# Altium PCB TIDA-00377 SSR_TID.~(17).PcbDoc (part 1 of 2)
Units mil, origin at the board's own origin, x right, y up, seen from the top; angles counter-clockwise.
Board outline 4300 x 2000 mil, 2 copper layers (Layer 1 - Top Layer, Layer 2 - Bottom Layer), stack 62 mil thick; 114 components, 37 nets, 228 pads, 275 vias.
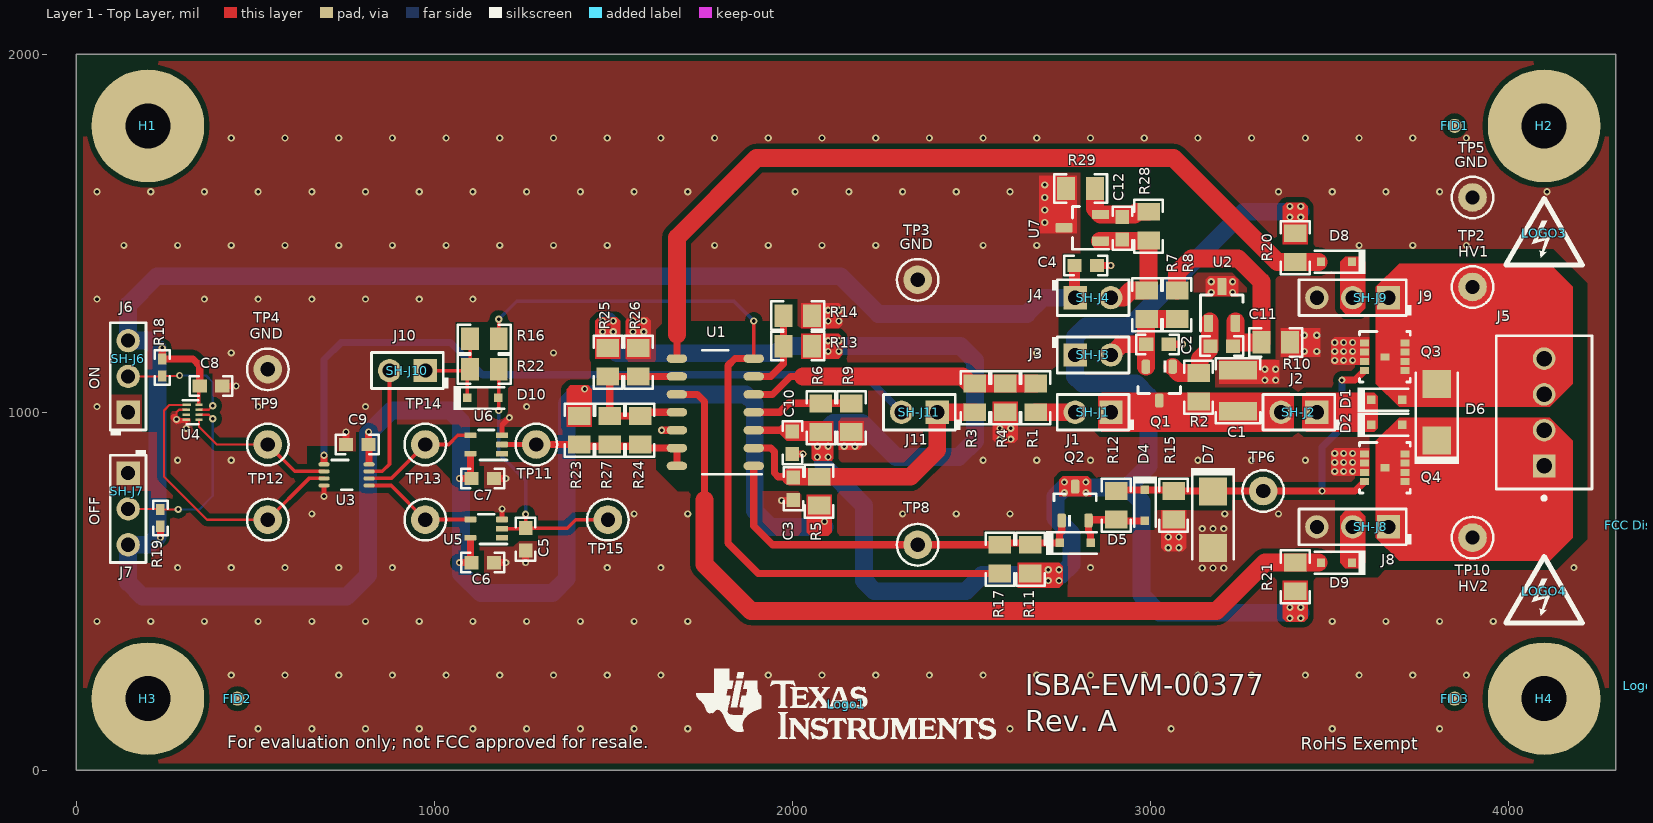
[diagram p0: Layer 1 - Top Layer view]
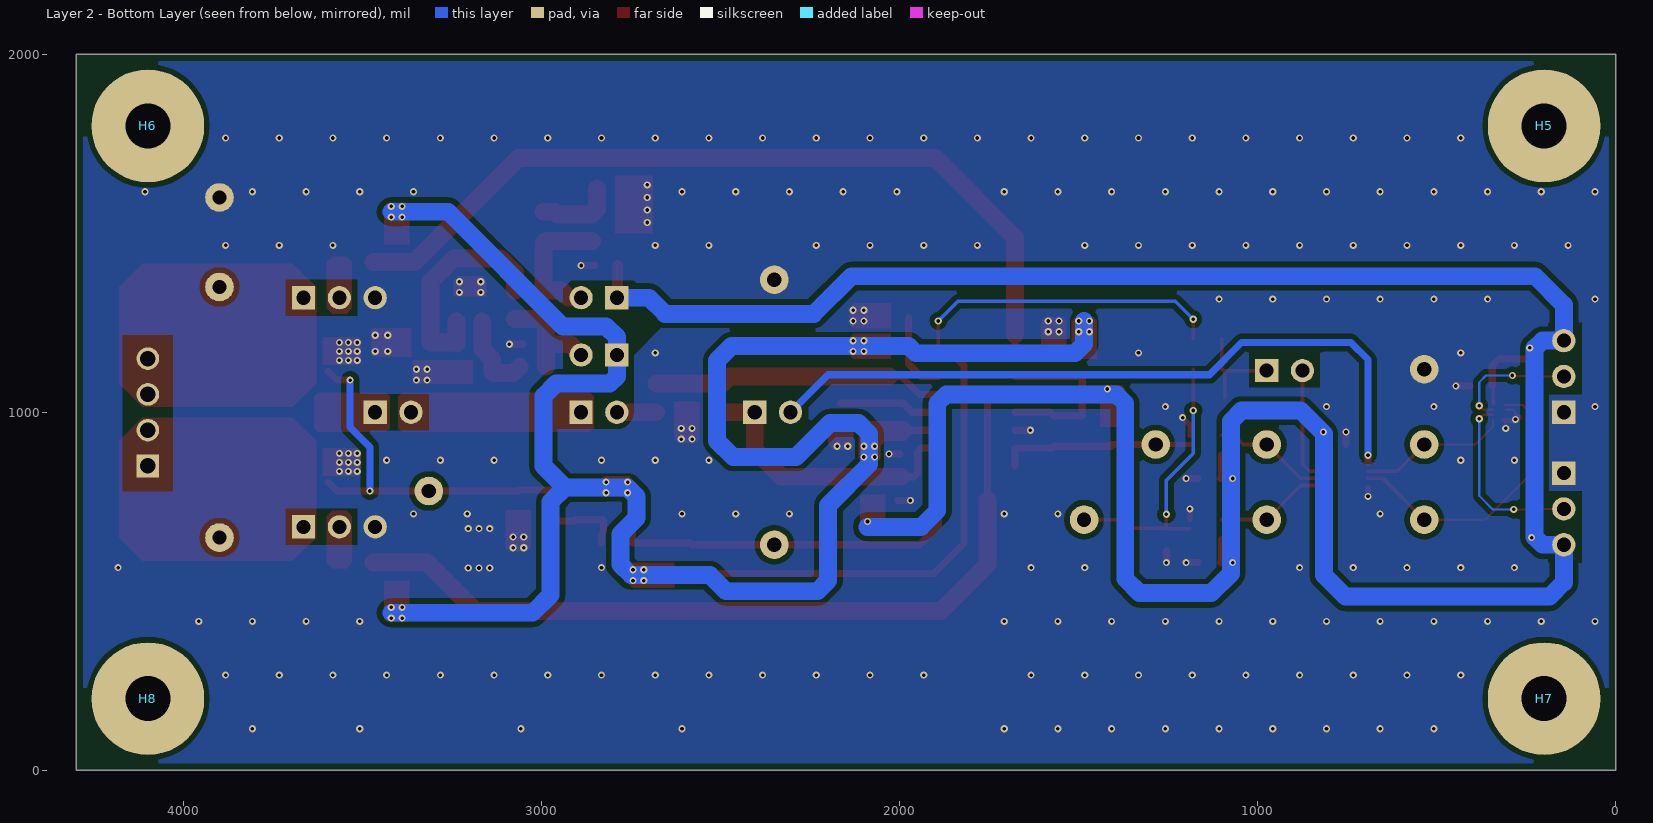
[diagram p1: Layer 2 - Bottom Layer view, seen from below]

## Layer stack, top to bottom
Top Solder: solder mask 0.4, Solder Resist, Dk 3.5
Layer 1 - Top Layer: signal copper 1.4
Dielectric1: core 59.2, 370HR, Dk 4.8
Layer 2 - Bottom Layer: signal copper 1.4
Bottom Solder: solder mask 0.4, Solder Resist, Dk 3.5

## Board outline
0,0 0,2000 4300,2000 4300,0

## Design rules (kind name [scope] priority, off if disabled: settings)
AcuteAngle [All] p1: minimum=4.50000000000000E+0001 checktracksonly=FALSE
AssemblyTestPointUsage [All] p1: valid=2
Clearance Clearance_Keepouts [((IsTrack Or IsArc) And Not InPoly) And IsFree and IsKeepOut vs ((IsTrack Or IsArc) And Not InPoly) And IsFree and IsKeepOut] p1: gap=0
Clearance Clearance_BoardEdge_MountingHoles [OnCopper and InComponentClass('Mounting Holes') vs IsKeepOut] p2: gap=40
Clearance Clearance_BoardEdge_Poly [OnCopper and InPoly vs IsKeepOut] p3: gap=20
Clearance Clearance_BoardEdge [OnCopper and Not InComponentClass('Logo') and not InComponentClass('FiducialMark') and not InRegion(1000,500,4000,800) and Not IsKeepout vs IsKeepOut] p4: gap=25
Clearance Clearance_Poly [InPolygon] p5: gap=15
Clearance [All] p6: gap=5.9
ComponentClearance ComponentClearance_MountingHoles_FiducialMarks [InComponentClass('Mounting Holes') vs InComponentClass('FiducialMark')] p1: gap=10 collisioncheckmode=3 verticalgap=10 showdistances=FALSE
ComponentClearance ComponentClearance_Shunt [InComponentClass('Header') vs InComponentClass('Shunt')] p2: gap=0 collisioncheckmode=3 verticalgap=0 showdistances=FALSE
ComponentClearance ComponentClearance_Logo [InComponentClass('Logo')] p3: gap=10 collisioncheckmode=3 verticalgap=10 showdistances=FALSE
ComponentClearance ComponentClearance_ScrewToNut [(HasFootprint('NY PMS 440 0025 PH')) vs (HasFootprint('Keystone_1902C'))] p4: gap=5 collisioncheckmode=3 verticalgap=10 showdistances=FALSE
ComponentClearance ComponentClearance_MountingHoles [InComponentClass('Mounting Holes')] p5: gap=10 collisioncheckmode=3 verticalgap=100000 showdistances=FALSE
ComponentClearance ComponentClearance_SmallPassives [HasFootprint('0201*') or HasFootprint('0402*') or HasFootprint('0508') or HasFootprint('0603*') or HasFootprint('0612') or HasFootprint('0805*') or HasFootprint('0815*') or HasFootprint('0830*') or HasFootprint('1206*') or HasFootprint('1210*') or HasFootprint('1808*') or HasFootprint('1812*') or HasFootprint('1825*') or HasFootprint('2010*') or HasFootprint('2220*') or HasFootprint('2225*') or HasFootprint('2512*') or HasFootprint('2728*') or HasFootprint('3518*') vs HasFootprint('0201*') or HasFootprint('0402*') or HasFootprint('0508') or HasFootprint('0603*') or HasFootprint('0612') or HasFootprint('0805*') or HasFootprint('0815*') or HasFootprint('0830*') or HasFootprint('1206*') or HasFootprint('1210*') or HasFootprint('1808*') or HasFootprint('1812*') or HasFootprint('1825*') or HasFootprint('2010*') or HasFootprint('2220*') or HasFootprint('2225*') or HasFootprint('2512*') or HasFootprint('2728*') or HasFootprint('3518*')] p6: gap=10 collisioncheckmode=3 verticalgap=10 showdistances=FALSE
ComponentClearance ComponentClearance_THtoSMT [IsThruComponent vs IsSMTComponent] p7: gap=10 collisioncheckmode=3 verticalgap=30 showdistances=FALSE
ComponentClearance ComponentClearance_THtoTH [IsThruComponent vs IsThruComponent] p8: gap=10 collisioncheckmode=3 verticalgap=30 showdistances=FALSE
ComponentClearance [All] p9: gap=10 collisioncheckmode=3 verticalgap=10 showdistances=FALSE
DiffPairsRouting [All] p1: maxlimit=100 minlimit=10 mostfreqgap=10 toplayer_minwidth=15 toplayer_maxwidth=15 toplayer_prefwidth=15 bottomlayer_minwidth=15 bottomlayer_maxwidth=15 bottomlayer_prefwidth=15 maxuncoupledlength=1000
FabricationTestPointUsage TestPointUsage [All] p1: valid=2 allowmultiple=FALSE
FabricationTestpoint Testpoint [All] p1: side=3 testpointundercomponent=TRUE minsize=40 maxsize=100 preferedsize=60 minholesize=0 maxholesize=40 preferedholesize=32 testpointgrid=1 allowsidetop=TRUE allowsidebottom=TRUE usegrid=TRUE gridtolerance=0.01
FanoutControl Fanout_LCC [IsLCC] p1: bgadir=Out bgaviamode=Centered fanoutstyle=Auto fanoutdirection=Alternating viagrid=1 // Fanout_LCC (Default Rule)
FanoutControl Fanout_BGA [IsBGA] p2: bgadir=Out bgaviamode=Centered fanoutstyle=Auto fanoutdirection=Alternating viagrid=1 // Fanout_BGA (Default Rule)
FanoutControl Fanout_Default [All] p4: bgadir=Out bgaviamode=Centered fanoutstyle=Auto fanoutdirection=Alternating viagrid=1 // Fanout_Default (Default Rule)
FanoutControl Fanout_Small [(CompPinCount < 5)] p5: bgadir=Out bgaviamode=Centered fanoutstyle=Auto fanoutdirection=OutThenIn viagrid=1 // Fanout_Small (Default Rule)
HoleSize [All] p1: absolutevalues=TRUE maxlimit=251 minlimit=8 maxpercent=80.000 minpercent=20.000
MinimumAnnularRing MinimumAnnularRing_ThermalPadVias [IsVia and InAnyComponent] p1: minimumring=5
MinimumAnnularRing [All] p2: minimumring=5
MinimumSolderMaskSliver MinimumSolderMaskSliver_Logo [InComponentClass('Logo') vs InComponentClass('Logo')] p1: minsoldermaskwidth=0.7
MinimumSolderMaskSliver [All] p2: minsoldermaskwidth=4
PlaneConnect [All] p1: planeconnectstyle=Relief reliefexpansion=10 reliefentries=4 reliefconductorwidth=10 reliefairgap=10
PolygonConnect [All] p1: connectstyle=Direct reliefconductorwidth=10 reliefentries=4 polygonreliefangle="90 Angle" airgapwidth=10
RoutingVias ThermalPadVias [IsVia and InAnyComponent] p1: holewidth=7.87 width=19.68 viastyle="Through Hole" minholewidth=7.87 minwidth=19.68 maxholewidth=12.99 maxwidth=23.62
RoutingVias [All] p2: holewidth=16 width=34 viastyle="Through Hole" minholewidth=7.87 minwidth=20 maxholewidth=40 maxwidth=65
SilkToBoardRegionClearance [Not ((IsComment or IsDesignator) And (Hide <> 'False')) and not InRegion(1000,500,4000,800)] p1:
SilkToSilkClearance SilkToSilkClearance_Pb-FreeLogo [(HasFootprint('Pb-Free_Overlay_Medium') OR HasFootprint('Pb-Free_Overlay_Small')) vs (HasFootprint('Pb-Free_Overlay_Medium') OR HasFootprint('Pb-Free_Overlay_Small'))] p1: silktosilkclearance=0
SilkToSilkClearance [All] p2: silktosilkclearance=4
SilkToSolderMaskClearance SilkToComonentPadClearance [IsPad and InAnycomponent] p1: minsilkscreentomaskgap=5 clearancetoexposedcopper=TRUE
SilkToSolderMaskClearance "Silk to Solder Mask Opening" [All] p2: minsilkscreentomaskgap=4 clearancetoexposedcopper=FALSE
SolderMaskExpansion [All] p1: expansion=1.97
Width [All] p1: maxlimit=100 minlimit=6 preferedwidth=10 checkconnectedcopper=TRUE
15 further rules are at their usual default settings.

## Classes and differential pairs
component class "TIDA-00377 SSR_Relay": C1 C2 C3 C4 C5 C6 C7 C8 C9 C10 C11 C12 D1 D2 D4 D5 D6 D7 D8 D9 D10 J1 J2 J3 J4 J5 J6 J7 J8 J9 J10 J11 Q1 Q2 Q3 Q4 R1 R2 R3 R4 R5 R6 R7 R8 R9 R10 R11 R12 R13 R14 R15 R16 R17 R18 R19 R20 R21 R22 R23 R24 R25 R26 R27 R28 R29 TP2 TP3 TP4 TP5 TP6 TP8 TP9 TP10 TP11 TP12 TP13 TP14 TP15 U1 U2 U3 U4 U5 U6 U7
component class Header: J1 J2 J3 J4 J6 J7 J8 J9 J10 J11
component class AssemblyNote: ZZ1 ZZ2 ZZ3
component class FiducialMark: FID1 FID2 FID3
component class "TIDA-00377 SSR_TID_Hardware": "FCC Disclaimer" FID1 FID2 FID3 H1 H2 H3 H4 H5 H6 H7 H8 Logo1 LOGO3 LOGO4 Logo? SH-J1 SH-J2 SH-J3 SH-J4 SH-J6 SH-J7 SH-J8 SH-J9 SH-J10 SH-J11 ZZ1 ZZ2 ZZ3
component class Logo: Logo1
component class "Mounting Holes": H1 H2 H3 H4
component class Shunt: SH-J1 SH-J2 SH-J3 SH-J4 SH-J6 SH-J7 SH-J8 SH-J9 SH-J10 SH-J11

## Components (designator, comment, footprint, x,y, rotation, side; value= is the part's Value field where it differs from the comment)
C1 "C3225X7S2A335M200AB" 1210 3245,1060 r270 top
C2 "GRM188R61E105KA12D" 0603 3020,1190 r180 top
C3 "GRM188R71E102KA01D" 0603 2003,786 r90 top
C4 "GRM188R61E105KA12D" 0603 2820,1410 r180 top
C5 "GRM188R71E102KA01D" 0603 1255,645 r90 top
C6 "GRM188R71C104KA01D" 0603 1135,580 r180 top
C7 "GRM188R71C104KA01D" 0603 1135,815 r180 top
C8 "GRM188R71C104KA01D" 0603 376.4,1073.3 r180 top
C9 "GRM188R71C104KA01D" 0603 785,910 r0 top
C10 "GRM188R71C104KA01D" 0603 2000,915 r90 top
C11 "GRM1885C1H201JA01D" 0603 3200,1184.68 r180 top
C12 "GRM1885C1H201JA01D" 0603 2922,1514.31 r270 top
D1 "1N4448WX-TP" sod-323 3660,1035 r0 top
D2 "1N4448WX-TP" sod-323 3660,965 r0 top
D4 "1N4448WX-TP" sod-323 2985,740 r270 top
D5 "1N4448WX-TP" sod-323 2790,635 r0 top
D6 "SMAJ78CA" SMA 3800,1000 r90 top
D7 "SMAZ18-13-F" SMA 3175,700 r270 top
D8 "1N4448WX-TP" sod-323 3520,1420 r180 top
D9 "1N4448WX-TP" sod-323 3520,580 r180 top
D10 "1N4448WX-TP" sod-323 1135,1040 r0 top
"FCC Disclaimer" "FCC disclaimer" FCC_disclaimer 4400,685 r90 top
FID1 "Fiducial" Fiducial10-20 3850,1800 r0 top
FID2 "Fiducial" Fiducial10-20 450,200 r0 top
FID3 "Fiducial" Fiducial10-20 3850,200 r0 top
H1 "NY PMS 440 0025 PH" "NY PMS 440 0025 PH" 200,1800 r0 top locked
H2 "NY PMS 440 0025 PH" "NY PMS 440 0025 PH" 4100,1800 r0 top locked
H3 "NY PMS 440 0025 PH" "NY PMS 440 0025 PH" 200,200 r0 top locked
H4 "NY PMS 440 0025 PH" "NY PMS 440 0025 PH" 4100,200 r0 top locked
H5 "1902C" Keystone_1902C 200,1800 r180 bottom locked
H6 "1902C" Keystone_1902C 4100,1800 r180 bottom locked
H7 "1902C" Keystone_1902C 200,200 r180 bottom locked
H8 "1902C" Keystone_1902C 4100,200 r180 bottom locked
J1 "5-146278-2" TE_5-146278-2 2840,1000 r180 top
J2 "5-146278-2" TE_5-146278-2 3415,1000 r180 top
J3 "5-146278-2" TE_5-146278-2 2840,1160 r0 top
J4 "5-146278-2" TE_5-146278-2 2840,1320 r0 top
J5 "282834-4" TEC_282834-4 4100,1000 r90 top
J6 "5-146278-3" TE_5-146278-3 145,1100 r90 top
J7 "5-146278-3" TE_5-146278-3 145,730 r270 top
J8 "5-146278-3" TE_5-146278-3 3565,680 r180 top
J9 "5-146278-3" TE_5-146278-3 3565,1320 r180 top
J10 "5-146278-2" TE_5-146278-2 925,1116.5 r180 top
J11 "5-146278-2" TE_5-146278-2 2355,1000 r180 top
Logo1 "Texas Instruments" TI_Stacked_Overlay_Small 2150,185 r0 top
LOGO3 "DANGER HIGH VOLTAGE" IEC_HighVoltage_Small 4100,1500 r0 top
LOGO4 "DANGER HIGH VOLTAGE" IEC_HighVoltage_Small 4100,500 r0 top
Logo? "EU RoHS Exempt Logo" EURoHS_Exempt_60mil 4373,236 r90 top
Q1 "DSC2C01R0L" SOT-23 3025,1080 r270 top
Q2 "MMBT3904LT1G" SOT-23 2790,745 r90 top
Q3 "CSD19537Q3" DQG0008A 3655,1155 r0 top
Q4 "CSD19537Q3" DQG0008A 3655,845 r0 top
R1 "CRCW080510M0FKEA" 0805_HV 2680,1040 r90 top
R2 "CRCW0805205KFKEA" 0805_HV 3135,1070 r90 top
R3 "CRCW08050000Z0EA" 0805_HV 2510,1040 r90 top
R4 "CRCW08051M43FKEA" 0805_HV 2595,1040 r270 top
R5 "CRCW0805100KFKEA" 0805_HV 2075,780 r90 top
R6 "CRCW080510M0FKEA" 0805_HV 2080,985 r90 top
R7 "CRCW0805100KFKEA" 0805_HV 2990,1300 r90 top
R8 "CRCW08053M74FKEA" 0805_HV 3075,1300 r90 top
R9 "CRCW08052M94FKEA" 0805_HV 2165,985 r270 top
R10 "CRCW08051M30FKEA" 0805_HV 3350,1195 r0 top
R11 "CRCW080593K1FKEA" 0805_HV 2665,590 r90 top
R12 "CRCW0805931RFKEA" 0805_HV 2905,740 r90 top
R13 "RC0805JR-0733ML" 0805_HV 2015,1185 r180 top
R14 "CRCW08056M49FKEA" 0805_HV 2015,1270 r0 top
R15 "CRCW0805422KFKEA" 0805_HV 3065,740 r90 top
R16 "CRCW08050000Z0EA" 0805_HV 1140,1205 r0 top
R17 "CRCW08050000Z0EA" 0805_HV 2580,590 r90 top
R18 "CRCW0402124KFKED" 0402 240,1125 r90 top
R19 "CRCW0402124KFKED" 0402 235,705 r270 top
R20 "RC0805JR-0733ML" 0805_HV 3405,1460 r270 top
R21 "RC0805JR-0733ML" 0805_HV 3405,540 r90 top
R22 "CRCW0805100KFKEA" 0805_HV 1140,1120 r0 top
R23 "CRCW0805402KFKEA" 0805_HV 1405,950 r270 top
R24 "CRCW08050000Z0EA" 0805_HV 1575,950 r90 top
R25 "CRCW080510M0FKEA" 0805_HV 1485,1140 r270 top
R26 "CRCW080510M0FKEA" 0805_HV 1570,1140 r90 top
R27 "CRCW08050000Z0EA" 0805_HV 1490,950 r90 top
R28 "CRCW0805806KFKEA" 0805_HV 2995,1520 r90 top
R29 "CRCW08052M80FKEA" 0805_HV 2805,1625 r180 top
SH-J1 "SPC02SYAN" SPC02SYAN 2840,1000 r180 top
SH-J2 "SPC02SYAN" SPC02SYAN 3415,1000 r180 top
SH-J3 "SPC02SYAN" SPC02SYAN 2840,1160 r180 top
SH-J4 "SPC02SYAN" SPC02SYAN 2840,1320 r180 top
SH-J6 "SPC02SYAN" SPC02SYAN 145,1150 r90 top
SH-J7 "SPC02SYAN" SPC02SYAN 142.5,780 r90 top
SH-J8 "SPC02SYAN" SPC02SYAN 3615,680 r180 top
SH-J9 "SPC02SYAN" SPC02SYAN 3615,1320 r180 top
SH-J10 "SPC02SYAN" SPC02SYAN 925,1116.5 r180 top
SH-J11 "SPC02SYAN" SPC02SYAN 2355,1000 r180 top
TP2 "5004" Keystone5004 3900,1350 r90 top
TP3 "5001" Keystone5001 2350,1370 r90 top
TP4 "5001" Keystone5001 535,1120 r90 top
TP5 "5001" Keystone5001 3900,1600 r90 top
TP6 "5001" Keystone5001 3315,780 r90 top
TP8 "5001" Keystone5001 2350,630 r90 top
TP9 "5001" Keystone5001 535,910 r90 top
TP10 "5004" Keystone5004 3900,650 r90 top
TP11 "5001" Keystone5001 1285,910 r90 top
TP12 "5001" Keystone5001 535,700 r90 top
TP13 "5001" Keystone5001 975,700 r90 top
TP14 "5001" Keystone5001 975,910 r90 top
TP15 "5001" Keystone5001 1485,700 r180 top
U1 "LP339D" D0014A_N 1785,1000 r180 top
U2 "ATL431AIDBZR" DBZ0003A_M 3200,1299.68 r90 top
U3 "SN74AUP2G08DCUR" DCU0008A_N 755,825 r0 top
U4 "SN74AUP1G74DQER" DQE0008A 325,1000 r0 top
U5 "SN74AUP1G17DCKR" DCK0005A_N 1145,675 r180 top
U6 "SN74AUP1G14DCKR" DCK0005A_N 1145,910 r180 top
U7 "ATL431AIDBZR" DBZ0003A_M 2810,1515.31 r180 top
ZZ1 "These assemblies are ESD sensitive, ESD precautions shall be observed." AssemblyNote 100,2400 r0 top
ZZ2 "These assemblies must be clean and free from flux and all contaminants. Use of no clean flux is not acceptable." AssemblyNote 100,2300 r0 top
ZZ3 "These assemblies must comply with workmanship standards IPC-A-610 Class 2, unless otherwise specified." AssemblyNote 100,2200 r0 top

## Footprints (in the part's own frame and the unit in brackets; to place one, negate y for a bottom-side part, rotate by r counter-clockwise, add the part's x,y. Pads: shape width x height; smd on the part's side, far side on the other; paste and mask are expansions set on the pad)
0402 [mm] "0402 from SM-752 data"
  rect 0.8x0.6 smd: 1(-0.6,0) 2(0.6,0)
  silkscreen extent -1.22,-0.52 1.22,0.52, body extent -0.55,-0.3 0.55,0.3, height 0.6
0603 [mm] "0603 from SM-752 data"
  rect 1x0.95 smd: 1(-0.8,0) 2(0.8,0)
  silkscreen extent -1.52,-0.69 1.52,0.69, body extent -0.87,-0.47 0.87,0.47, height 1
0805_HV [mil] "0805 with 30mil clearance between pads"
  rect 50x63 smd: 1(-40,0) 2(40,0)
  silkscreen extent -74,-40 74,40, body extent -43,-29 43,29, height 57
1210 [mm] "1210 from SM-752 data"
  rect 1.3x2.7 smd: 1(-1.45,0) 2(1.45,0)
  silkscreen extent -2.32,-1.57 2.32,1.57, body extent -1.7,-1.35 1.7,1.35, height 1.35
AssemblyNote [mil] "Assembly Note"
D0014A_N [mm] "SOIC, 14-Leads, Body 8.7x3.9mm, Pitch 1.27mm, IPC Medium Density"
  oval 1.45x0.6 smd: 1(-2.725,3.81) 2(-2.725,2.54) 3(-2.725,1.27) 4(-2.725,0) 5(-2.725,-1.27) 6(-2.725,-2.54) 7(-2.725,-3.81) 8(2.725,-3.81) 9(2.725,-2.54) 10(2.725,-1.27) 11(2.725,0) 12(2.725,1.27) 13(2.725,2.54) 14(2.725,3.81)
  silkscreen extent -3.3,-4.4 0.9,4.4, body extent -3.02,-4.32 3.02,4.32, height 1.6
DBZ0003A_M [mm] "SOT23, 3-Leads, Body 2.9x1.3mm, Pitch 0.95mm, Lead Span 2.4mm, IPC Low Density"
  rrect15% 1.2x0.65 smd: 1(-1.3,0.95) 2(-1.3,-0.95) 3(1.3,0)
  silkscreen extent -1.85,-1.5 0.7,1.53, body extent -1.26,-1.46 1.26,1.46, height 0.98
DCK0005A_N [mm] "SOT353, 5-Leads, Body 2x1.3mm, Pitch 0.65mm, Lead Span 2.1mm, IPC Medium Density"
  rrect25% 0.85x0.4 smd: 1(-1.125,0.65) 2(-1.125,0) 3(-1.125,-0.65) 4(1.125,-0.65) 5(1.125,0.65)
  silkscreen extent -1.48,-1.02 0.55,1.1, body extent -1.14,-1 1.14,1, height 0.95
DCU0008A_N [mm] "TSSOP, 8-Leads, Body 2x2.3mm, Pitch 0.5mm, IPC Medium Density"
  oval 0.8x0.3 smd mask+0.025: 1(-1.6,0.75) 2(-1.6,0.25) 3(-1.6,-0.25) 4(-1.6,-0.75) 5(1.6,-0.75) 6(1.6,-0.25) 7(1.6,0.25) 8(1.6,0.75)
  silkscreen extent -1.05,-1.05 0.38,1.05, body extent -1.56,-1 1.56,1, height 0.9
DQE0008A [mm] "SON, 8-Leads, Body 1.4x1mm, Pitch 0.35mm, TI Recommended"
  rect 0.6x0.16 smd: 1(-0.4,0.525)
  rect 0.5x0.16 smd mask+0.025: 2(-0.45,0.175) 3(-0.45,-0.175) 4(-0.45,-0.525) 5(0.45,-0.525) 6(0.45,-0.175) 7(0.45,0.175) 8(0.45,0.525)
  silkscreen extent -0.7,-0.85 0.4,0.85, body extent -0.53,-0.72 0.53,0.73, height 0.41
DQG0008A [mm] "SMD, 8-Leads, Body 3.3x3.3mm, Pitch 0.65mm"
  rect 0.63x0.5 smd paste-0.4 mask+0: 1(-1.435,0.975) 2(-1.435,0.325) 3(-1.435,-0.325) 4(-1.435,-0.975) 5(1.435,-0.975) 6(1.435,-0.325) 7(1.435,0.325) 8(1.435,0.975) 9(0,0)
  Layer 1 - Top Layer region: -0.56,1.225 -0.56,-1.225 1.34,-1.225 1.34,1.225
  silkscreen extent -1.8,-1.8 1.8,1.8, body extent -1.65,-1.65 1.65,1.65, height 1.1
EURoHS_Exempt_60mil [mil] "EU RoHS Exempt symbol"
FCC_disclaimer [mil]
Fiducial10-20 [mm]
  round 1 smd mask+0.5: 1(0,0)
IEC_HighVoltage_Small [mil]
  silkscreen extent -107,-88 107,97
Keystone5001 [mil] "For Keystone 500x miniature loop terminals"
  round 80 hole 40: 1(0,0)
  silkscreen extent -58,-58 58,58, body extent -49,-49 49,49, height 182
Keystone5004 [mil] "For Keystone 500x miniature loop terminals"
  round 80 hole 40: 1(0,0)
  silkscreen extent -58,-58 58,58, body extent -49,-49 49,49, height 182
Keystone_1902C [mil] "Hex Standoff, 4-40 threaded, nylon"
  body extent -145,-126 146,126, height 501
"NY PMS 440 0025 PH" [mm] "4-40 nylon screw and mounting hole"
  round 8 hole 3.2: 1(0,0)
  body extent -3.3,-3.3 3.3,3.3, height 2.69
SMA [mm] "Molded Diode, 2-Leads, Body 4.3x2.6mm, IPC Medium Density, based on OnSemi component dimensions and land pattern"
  rect 2x2 smd: 1(-2,0) 2(2,0)
  silkscreen extent -3.66,-1.57 2.79,1.57, body extent -2.6,-1.3 2.6,1.3, height 2.42
sod-323 [mm] "NXP recommended land pattern"
  rect 0.6x0.6 smd paste-0.05: 1(-1.1,0) 2(1.1,0)
  silkscreen extent -2.06,-0.86 1.53,0.86, body extent -1.3,-0.67 1.3,0.68, height 1.1
SOT-23 [mm] "SOT23, 3-Leads, Body 2.9x1.3mm, Pitch 0.95mm, Lead Span 2.5mm, IPC Medium Density"
  rrect50% 1x0.6 smd: 1(-1.2,0.95) 2(-1.2,-0.95) 3(1.2,0)
  silkscreen extent -1.63,-1.5 0.7,1.5, body extent -1.16,-1.45 1.21,1.45, height 1
SPC02SYAN [mil] "SULLINS"
  round 1 on Mech3: 0(0,0)
  body extent -98,-47 99,47, height 366
TE_5-146278-2 [mm] "TE CONNECTIVITY"
  rect 1.65x1.65 hole 1: 1(-1.27,0)
  round 1.65 hole 1: 2(1.27,0)
  silkscreen extent -2.92,-1.27 2.54,1.27, body extent -2.41,-1.17 2.41,1.17, height 8.13
TE_5-146278-3 [mm] "TE CONNECTIVITY"
  rect 1.65x1.65 hole 1: 1(-2.54,0)
  round 1.65 hole 1: 2(0,0) 3(2.54,0)
  silkscreen extent -4.19,-1.27 3.81,1.27, body extent -3.68,-1.17 3.68,1.17, height 8.13
TEC_282834-4 [mm] "TEC"
  rect 1.6x1.6 hole 1.1: 1(-3.81,0)
  round 1.6 hole 1.1: 2(-1.27,0) 3(1.27,0) 4(3.81,0)
  silkscreen extent -6.2,-3.4 5.44,3.4, body extent -5.31,-3.25 5.31,3.25, height 10.02
TI_Stacked_Overlay_Small [mil]
  silkscreen extent -418,-98 418,98

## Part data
C1: "CAP, CERM, 3.3 µF, 100 V, +/- 20%, X7S, 1210"
C2 C4: "CAP, CERM, 1 µF, 25 V, +/- 10%, X5R, 0603"
C3 C5: "CAP, CERM, 1000 pF, 25 V, +/- 10%, X7R, 0603"
C6 C7 C8 C9 C10: "CAP, CERM, 0.1 µF, 16 V, +/- 10%, X7R, 0603"
C11 C12: "CAP, CERM, 200 pF, 50 V, +/- 5%, C0G/NP0, 0603"
D1 D2 D4 D5 D8 D9 D10: "Diode, Switching, 75 V, 0.25 A, SOD-323"
D6: "Diode, TVS, Bi, 78 V, 400 W, SMA"
D7: "Diode, Zener, 18 V, 1 W, AEC-Q101, SMA"
"FCC Disclaimer": library part FCC_disclaimer, "FCC_disclaimer"
FID1 FID2 FID3: "Fiducial mark.  There is nothing to buy or mount."
H1 H2 H3 H4: "Machine Screw, Round, #4-40 x 1/4, Nylon, Philips panhead"
H5 H6 H7 H8: "Standoff, Hex, 0.5\"L #4-40 Nylon"
J1 J2 J3 J4 J10 J11: "Header, 100mil, 2x1, Tin, TH"
J5: "Terminal Block, 100mil, 4X1 TH"
J6 J7 J8 J9: "Header, 100mil, 3x1, Tin, TH"
Logo1: library part TI_Logo, "Texas Instrument Corporate Signature"
LOGO3 LOGO4: library part IEC_HighVoltage, "IEC 61010-1 High Voltage Warning"
Logo?: library part EURoHS_Exempt
Q1: library part "DSC2C01R0L, Panasonic", "Transistor, NPN, 100 V, 0.02 A, SOT-23"
Q2: library part "MMBT3904LT1G, ON Semiconductor", "Transistor, NPN, 40 V, 0.2 A, SOT-23"
Q3 Q4: "MOSFET, N-CH, 100 V, 50 A, DQG0008A"
R1 R6 R25 R26: "RES, 10.0 M, 1%, 0.125 W, 0805"
R2: "RES, 205 k, 1%, 0.125 W, 0805"
R3 R16 R17 R24 R27: "RES, 0, 5%, 0.125 W, 0805"
R4: "RES, 1.43 M, 1%, 0.125 W, 0805"
R5 R7 R22: "RES, 100 k, 1%, 0.125 W, 0805"
R8: "RES, 3.74 M, 1%, 0.125 W, 0805"
R9: "RES, 2.94 M, 1%, 0.125 W, 0805"
R10: "RES, 1.30 M, 1%, 0.125 W, 0805"
R11: "RES, 93.1 k, 1%, 0.125 W, 0805"
R12: "RES, 931, 1%, 0.125 W, 0805"
R13 R20 R21: "RES, 33 M, 5%, 0.125 W, 0805"
R14: "RES, 6.49 M, 1%, 0.125 W, 0805"
R15: "RES, 422 k, 1%, 0.125 W, 0805"
R18 R19: "RES, 124 k, 1%, 0.063 W, 0402"
R23: "RES, 402 k, 1%, 0.125 W, 0805"
R28: "RES, 806 k, 1%, 0.125 W, 0805"
R29: "RES, 2.80 M, 1%, 0.125 W, 0805"
SH-J1 SH-J2 SH-J3 SH-J4 SH-J6 SH-J7 SH-J8 SH-J9 SH-J10 SH-J11: "Shunt, 100mil, Flash Gold, Black"
TP2 TP10: "Test Point, Miniature, Yellow, TH"
TP3 TP4 TP5 TP6 TP8 TP9 TP11 TP12 TP13 TP14 TP15: "Test Point, Miniature, Black, TH"
U1: "Quad, Low-Power, General Purpose Differential Comparator, D0014A"
U2 U7: "2.5V Low Iq Adjustable Precision Shunt Regulator, DBZ0003A"
U3: "LOW-POWER DUAL 2-INPUT POSITIVE-AND GATE, DCU0008A"
U4: "LOW-POWER SINGLE POSITIVE-EDGE-TRIGGERED D-TYPE FLIP-FLOP WITH CLEAR AND PRESET, DQE0008A"
U5: "LOW-POWER SINGLE SCHMITT-TRIGGER BUFFER, DCK0005A"
U6: "LOW-POWER SINGLE SCHMITT-TRIGGER INVERTER, DCK0005A"
ZZ1 ZZ2 ZZ3: library part AssemblyNote

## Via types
v1: diameter 20, hole 10, Layer 1 - Top Layer to Layer 2 - Bottom Layer, tented both sides, 275 vias

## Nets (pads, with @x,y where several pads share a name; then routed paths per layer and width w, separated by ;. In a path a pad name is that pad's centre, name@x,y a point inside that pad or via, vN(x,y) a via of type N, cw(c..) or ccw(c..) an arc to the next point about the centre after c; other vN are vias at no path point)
3.3V: C4.2 C6.2 C7.2 C8.2 C9.2 J4.1 J6.3 J7.3 R5.1 R18.2 R19.2 R23.1 U3.8 U4.8 U5.5 U6.5 | length 8014.6
  Layer 1 - Top Layer w10: U4.8@342.72,1023.3 C8.2@342.72,1071.11
  Layer 1 - Top Layer w20: v1(235,650) R19.2@235,681.38 ; v1(240,1180) R18.2@240,1148.62 326.38,1148.62 344.9,1130.1 C8.2@344.9,1073.3 ; C9.2@816.5,910 v1(816.5,945) ; U3.8@817.99,859 C9.2@817.99,908.5 ; v1(1070,580) C6.2@1103.5,580 ; v1(1070,815) C7.2@1103.5,815 ; C6.2@1100.71,582.8 U5.5@1100.71,645 ; C7.2@1100.71,817.8 U6.5@1100.71,880
  Layer 1 - Top Layer w30: J4.1@2788.5,1321.5 C4.2@2788.5,1410
  Layer 2 - Bottom Layer w50: 227.13,1180 227.13,1177.87 ; 2090,680 1940,680 1895,725 1895,1025 1870,1050 1395,1050 1370,1025 1370,535 1330,495 1130,495 1075,550 1075,975 1045,1005 880,1005 815,940 815,545 755,485 185,485 145,525 J7.3@145,630 205,630 227.13,652.13 227.13,1177.87 ; J4.1@2790,1320 2700,1320 2655,1275 2240,1275 2135,1380 225,1380 145,1300 J6.3@145,1200 205,1200 227.13,1177.87
  other v1: 2090,695 1420,1065
10V: C10.2 J3.1 Q2.3 R6.1 R11.1 R13.1 R20.1 R21.1 R25.1 U1.3 | length 5634.8
  Layer 1 - Top Layer w20: U1.3@1892.28,950 C10.2@1996.5,950 ; C10.2@2000,946.5 C10.2@1996.5,950 ; C10.2@2001.5,950 C10.2@1996.5,950
  Layer 2 - Bottom Layer w50: 1485,1255 1485,1190 1510,1165 1955,1165 1975,1185 2470,1185 2510,1145 2510,920 2465,875 2290,875 2195,970 2115,970 2085,940 2085,855 2200,740 2200,530 2230,500 2485,500 2530,545 2750,545 2780,575 2780,660 2735,705 2735,765 2760,790 2935,790 ; 3420,440 3025,440 2975,490 2975,750 2935,790 ; 3420,1560 3261,1560 2941,1240 2820,1240 2790,1210 J3.1@2790,1160 2790,1100 2810,1080 2960,1080 2995,1045 2995,850 2935,790
  other v1: 3390,425 3420,425 3390,455 3420,455 2715,530 2745,530 2715,560 2745,560 2760,775 2820,775 2760,805 2820,805 2070,875 2100,875 2070,905 2100,905 2100,1170 2130,1170 2100,1200 2130,1200 1470,1225 1500,1225 1470,1255 1500,1255 3390,1545 3420,1545 3390,1575 3420,1575
GND: C1.1 C2.1 C3.1 C4.1 C5.1 C6.1 C7.1 C8.1 C9.1 C10.1 D7.2 J6.1 J7.1 J8.3 J9.3 Q3.1 Q3.2 Q3.3 Q4.1 Q4.2 Q4.3 R4.2 R9.2 R10.2 R14.2 R15.1 R26.2 R29.2 TP3.1 TP4.1 TP5.1 U1.12 U2.3 U3.4 U4.2 U4.4 U5.3 U6.3 U7.3 | length 545.6
  Layer 1 - Top Layer w6: v1(280,980) 280,1000 286.89,1006.89 U4.2@307.28,1006.89 ; v1(307.28,955) U4.4@307.28,979.33
  Layer 1 - Top Layer w15: v1(692.01,765) U3.4@692.01,790 ; U5.3@1189.29,700.59 v1(1189.29,730) ; U6.3@1189.29,935.59 1189.29,964.29 v1(1210,985)
  Layer 1 - Top Layer w20: C8.1@407.9,1073.3 v1(446.4,1073.3) ; C9.1@753.5,910 v1(753.5,945) ; C6.1@1166.5,580 v1(1200,580) ; C7.1@1166.5,815 v1(1200,815) ; v1(1255,580) C5.1@1255,613.5 ; v1(1635,950) U1.12@1677.72,950 ; v1(1970,753.5) C3.1@2005,753.5 ; C10.1@2000,883.5 v1(2030,883.5) ; C4.1@2851.5,1410 v1(2890,1410) ; C2.1@3051.5,1190 v1(3090,1190)
  other v1: 508,116 658,116 808,116 958,116 1108,116 1258,116 1408,116 1558,116 1708,116 2608,116 3058,116 3508,116 3808,116 433,266 583,266 733,266 883,266 1033,266 1183,266 1333,266 1483,266 1633,266 1933,266 2083,266 2233,266 2383,266 2533,266 2683,266 2833,266 2983,266 3133,266 3283,266 3433,266 3583,266 3733,266 3883,266 58,416 208,416 358,416 508,416 658,416 808,416 958,416 1108,416 1258,416 1408,416 1558,416 1708,416 3508,416 3658,416 3808,416 3958,416 3145,565 3175,565 3205,565 283,566 433,566 583,566 733,566 883,566 1483,566 1633,566 2833,566 4183,566 3050,621.7 3080,621.7 3050,651.7 3080,651.7 3145,675 3175,675 3205,675 658,716 1558,716 1708,716 2308,716 2458,716 2608,716 3208,716 3358,716 3515,835 3540,835 3565,835 3515,860 3540,860 3565,860 283,866 433,866 2533,866 2683,866 2833,866 3133,866 3283,866 3433,866 3515,885 3540,885 3565,885 2145,905 2175,905 2580,925 2610,925 2580,955 2610,955 58,1016 508,1016 808,1016 1258,1016 3320,1090 3350,1090 3320,1120 3350,1120 3515,1145 3540,1145 3565,1145 433,1166 1333,1166 2683,1166 3430,1170 3465,1170 3515,1170 3540,1170 3565,1170 3515,1195 3540,1195 3565,1195 3430,1215 3465,1215 1555,1225 1585,1225 1555,1255 1585,1255 2100,1255 2130,1255 2100,1285 2130,1285 58,1316 358,1316 508,1316 658,1316 808,1316 958,1316 1108,1316 3170,1334.68 3230,1334.68 3170,1364.68 3230,1364.68 133,1466 283,1466 433,1466 583,1466 733,1466 883,1466 1033,1466 1183,1466 1333,1466 1483,1466 1783,1466 1933,1466 2083,1466 2233,1466 2533,1466 2683,1466 3583,1466 3733,1466 3883,1466 2705,1530 2705,1565 2705,1600 58,1616 208,1616 358,1616 508,1616 658,1616 808,1616 958,1616 1108,1616 1258,1616 1408,1616 1558,1616 1708,1616 2008,1616 2158,1616 2308,1616 2458,1616 2608,1616 3358,1616 3508,1616 3658,1616 3808,1616 4108,1616 2705,1635 433,1766 583,1766 733,1766 883,1766 1033,1766 1183,1766 1333,1766 1483,1766 1633,1766 1783,1766 1933,1766 2083,1766 2233,1766 2383,1766 2533,1766 2683,1766 2833,1766 2983,1766 3133,1766 3283,1766 3433,1766 3583,1766 3733,1766 3883,1766
HV1: D1.2 D6.2 J5.3 J5.4 J9.1 Q3.5 Q3.6 Q3.7 Q3.8 Q3.9 TP2.1
HV2: D2.2 D6.1 J5.1 J5.2 J8.1 Q4.5 Q4.6 Q4.7 Q4.8 Q4.9 TP10.1
NetC1_2: C1.2 J1.1 J2.2 Q1.3 R2.1
NetC2_2: C2.2 J3.2 Q1.2 R7.1 R8.1 | length 325.4
  Layer 1 - Top Layer w50: J3.2@2890,1160 2920,1190 C2.2@2987.6,1190 ; Q1.2@2987.6,1127.24 C2.2@2987.6,1190 ; R7.1@2987.6,1256.71 C2.2@2987.6,1190 ; C2.2@2988.5,1190 C2.2@2987.6,1190 ; R7.1@2990,1260 R8.1@3075,1260
NetC3_2: C3.2 J11.1 R3.1 R5.2 U1.2 | length 822.1
  Layer 1 - Top Layer w20: U1.2@1892.28,900 1940,900 1950,890 1950,830 1960,820 C3.2@1995,820
  Layer 1 - Top Layer w50: C3.2@1995,820 R5.2@2075,820 2330,820 2405,895 J11.1@2405,1000 R3.1@2510,1000
NetC5_2: C5.2 D10.2 R22.2 TP15.1 U5.2 | length 778.5
  Layer 1 - Top Layer w10: v1(1180,1005) R22.2@1180,1120 ; U5.2@1189.29,675 C5.2@1253.5,675 ; v1(1255,715) C5.2@1255,676.5 1371.5,676.5 1395,700 TP15.1@1485,700
  Layer 2 - Bottom Layer w10: v1(1180,1005) 1180,885 1255,810 v1(1255,715)
NetC11_1: C11.1 R8.2 R10.1 U2.2 | length 623.9
  Layer 1 - Top Layer w50: R8.2@3075,1340 3075,1390 3115,1430 3245,1430 3310,1365 R10.1@3310,1195 C11.1@3245,1195 ; C11.1@3237.4,1192.6 U2.2@3237.4,1248.5 U2.2@3237.4,1253
NetC11_2: C11.2 Q1.1 R2.2 U2.1 | length 235.6
  Layer 1 - Top Layer w50: Q1.1@3062.4,1127.24 3079.65,1110 R2.2@3135,1110 3138,1113 3138,1149 3166,1177 U2.1@3166,1253
NetC12_1: C12.1 R28.2 R29.1 U7.2 | length 215.8
  Layer 1 - Top Layer w50: R29.1@2845,1625 2845,1568.9 U7.2@2861.18,1552.72 2955.72,1552.72 2963,1560 R28.2@2995,1560
NetC12_2: C12.2 J4.2 R7.2 R28.1 U7.1 | length 380.4
  Layer 1 - Top Layer w50: U7.1@2859,1477.91 U7.1@2861.18,1477.91 2988.4,1477.91 2995,1471.32 2995,1345 R7.2@2990,1340 2945,1340 2925,1320 J4.2@2890,1320
NetD1_1: D1.1 D2.1 J2.1
NetD4_1: D4.1 D7.1 Q3.4 Q4.4 R12.2 R15.2 TP6.1 | length 1107.9
  Layer 1 - Top Layer w20: R12.2@2905,780 2908.3,783.31 D4.1@2985,783.31 3061.69,783.31 R15.2@3065,780 3173.74,780 D7.1@3175,778.74 ; D7.1@3175,780 TP6.1@3315,780 v1(3480,780) 3571.89,780 Q4.4@3595.94,804.06 ; v1(3535,1090) 3571.89,1090 Q3.4@3595.94,1114.06
  Layer 2 - Bottom Layer w20: v1(3480,780) 3480,903 3535,958 v1(3535,1090)
NetD4_2: D4.2 D5.2 Q2.2 R12.1 | length 225.1
  Layer 1 - Top Layer w20: D5.2@2833.3,635 2833.3,661.7 2827.4,667.6 Q2.2@2827.4,697.76 2829.64,700 R12.1@2905,700 2908.3,696.7 D4.2@2985,696.7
